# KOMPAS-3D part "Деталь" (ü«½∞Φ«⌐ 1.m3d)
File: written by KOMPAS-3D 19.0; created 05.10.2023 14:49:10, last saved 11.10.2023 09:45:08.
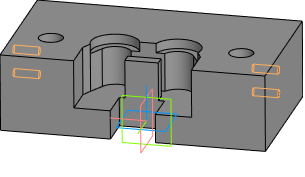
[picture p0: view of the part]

Document properties: Автор: admin; Организация: Hewlett-Packard Company; Полное имя файла: C:\Users\Petrenko-VE\Desktop\пресса 50 т\оправка два больших подшипника\Большой_1.m3d

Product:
- Part/product: Деталь
    Масса: 22.628
  - Body: Тело 1
      Масса: 22.6886

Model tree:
1. Эскиз:1
2. Элемент выдавливания:1
     Расстояние 1 = 80
3. Эскиз:2  (with: Элемент выдавливания:1)
4. Элемент выдавливания:2
     Расстояние 2 = 10
5. Эскиз:3  (with: Элемент выдавливания:1)
6. Элемент выдавливания:3
     Расстояние 2 = 80
7. Эскиз:4  (with: Элемент выдавливания:1)
8. Эскиз:5  (with: Элемент выдавливания:1)
9. Элемент выдавливания:4
     Расстояние 2 = 40
10. Эскиз:6  (with: Элемент выдавливания:1, Элемент выдавливания:4)
11. Элемент выдавливания:5
     Расстояние 2 = 80
12. Эскиз:7  (with: Элемент выдавливания:1, Элемент выдавливания:5)
13. Элемент выдавливания:6
     Расстояние 2 = 80
14. Эскиз:8  (with: Элемент выдавливания:4, Элемент выдавливания:5)
15. Элемент выдавливания:7
     Расстояние 1 = 30
16. Эскиз:9  (with: Элемент выдавливания:7, Элемент выдавливания:5)
17. Элемент выдавливания:8
     Расстояние 1 = 55
18. Скругление:1  (with: Элемент выдавливания:8)
     Радиус = 10
19. Эскиз:10  (with: Элемент выдавливания:1, Элемент выдавливания:5)
20. Элемент выдавливания:9
21. Элемент выдавливания:10  (with: Элемент выдавливания:4)
     Расстояние 2 = 10
22. Эскиз:11  (with: Элемент выдавливания:1, Элемент выдавливания:3)
23. Элемент выдавливания:11
     Расстояние 2 = 80
24. Эскиз:12  (with: Элемент выдавливания:1)
25. Элемент выдавливания:12
     Расстояние 2 = 80
26. Эскиз:13  (with: Элемент выдавливания:7, Элемент выдавливания:9)
27. Элемент выдавливания:13
     Расстояние 1 = 80
28. Эскиз:14  (with: Элемент выдавливания:1, Элемент выдавливания:13, Элемент выдавливания:4)
29. Элемент выдавливания:14
     Расстояние 2 = 50
30. Эскиз:15  (with: Элемент выдавливания:1, Элемент выдавливания:13, Элемент выдавливания:4)
31. Элемент выдавливания:15
     Расстояние 2 = 50
32. Эскиз:16  (with: Элемент выдавливания:1, Элемент выдавливания:9)
33. Элемент выдавливания:16
     Расстояние 2 = 40
34. Условное изображение резьбы:1  (with: Элемент выдавливания:16)  (labels: M8; cil0_24705-2004 coarse)
     Длина резьбы = 26.1573; Шаг резьбы = 1.25; Номинальный диаметр резьбы = 8
35. Подгонка:1  (with: Элемент выдавливания:16)
36. Условное изображение резьбы:2  (with: Элемент выдавливания:16)  (labels: M8; cil0_24705-2004 coarse)
     Длина резьбы = 26.1573; Шаг резьбы = 1.25; Номинальный диаметр резьбы = 8
37. Подгонка:2  (with: Элемент выдавливания:16)
38. Эскиз:17  (with: Элемент выдавливания:1)
39. Элемент выдавливания:17
     Расстояние 2 = 40
40. Условное изображение резьбы:3  (with: Элемент выдавливания:17)  (labels: M8; cil0_24705-2004 coarse)
     Длина резьбы = 26.1573; Шаг резьбы = 1.25; Номинальный диаметр резьбы = 8
41. Подгонка:3  (with: Элемент выдавливания:17)
42. Условное изображение резьбы:4  (with: Элемент выдавливания:17)  (labels: M8; cil0_24705-2004 coarse)
     Длина резьбы = 26.1573; Шаг резьбы = 1.25; Номинальный диаметр резьбы = 8
43. Подгонка:4  (with: Элемент выдавливания:17)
